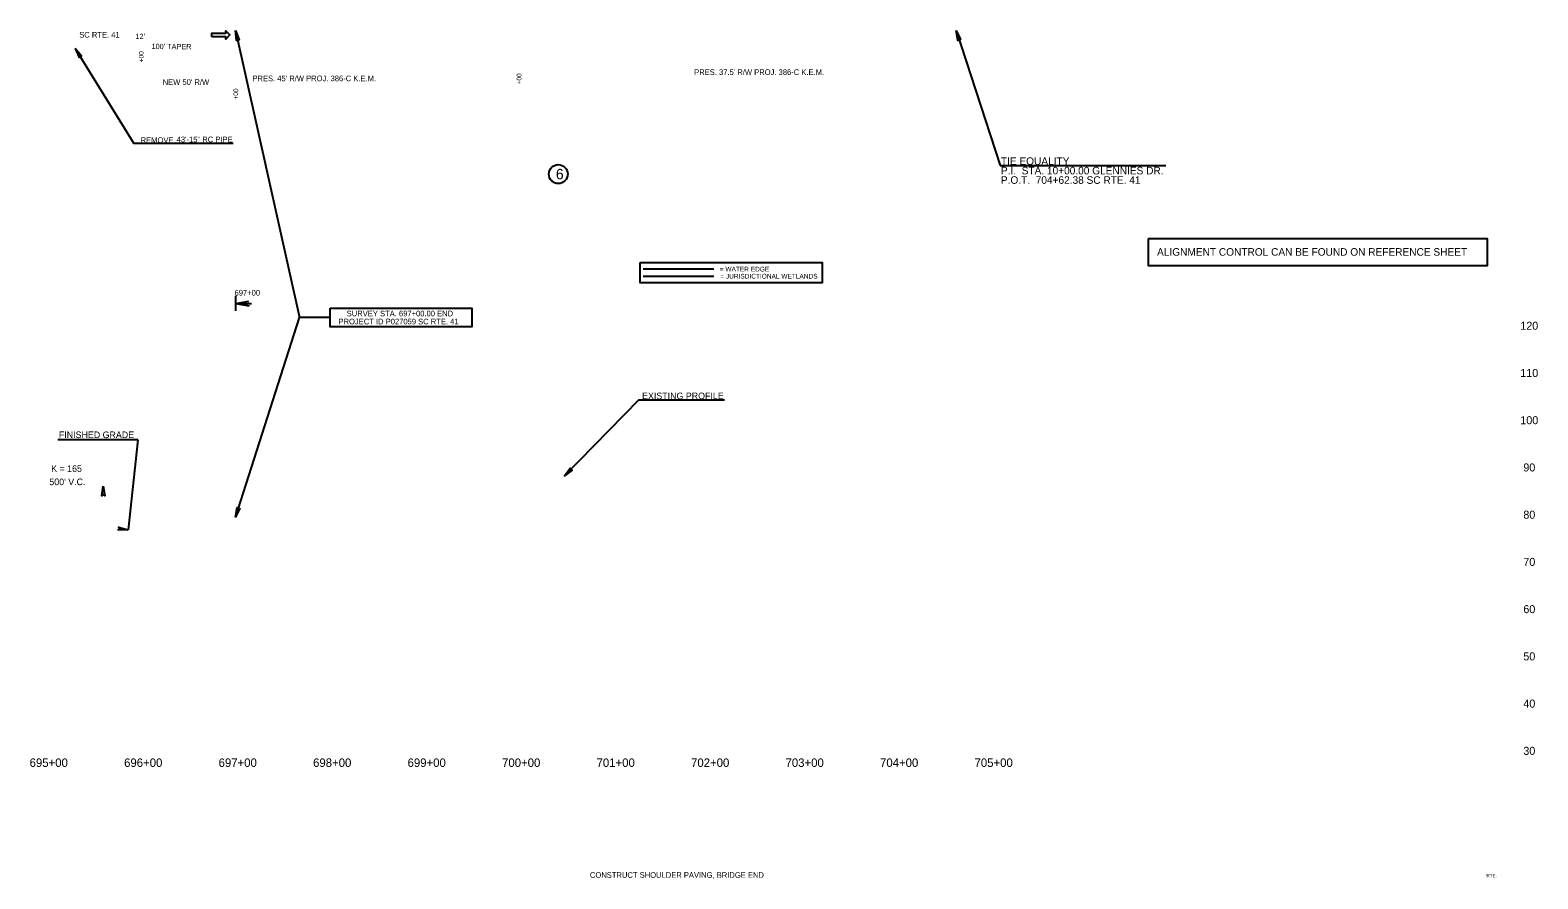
# Model space of a CAD drawing. Extents: x 2522404 to 2525275, y 885432 to 893540.
# Drawn here: x 2523395 to 2524991, y 888858 to 889756 of the extents above; entities that cross this region are included whole.
import ezdxf

# ---------------------------------------------------------------- set-up
doc = ezdxf.new("R2010")
doc.units = 0
for name, color, linetype in [('Default', 7, 'Continuous'), ('GN_Clip', 7, 'Continuous'), ('RD_DDB_ElevTX', 7, 'Continuous'), ('RD_DDB_Profile_Lbl', 7, 'Continuous'), ('RD_DDB_Profile_PR', 7, 'Continuous'), ('RD_DDB_StaTX', 7, 'Continuous'), ('RD_EV_JW', 7, 'Continuous'), ('RD_EX_H2O', 7, 'Continuous'), ('RD_EX_Misc', 7, 'Continuous'), ('RD_HC_Cl', 7, 'Continuous'), ('RD_HC_TX_Sta50', 7, 'Continuous'), ('RD_HY_TX1', 7, 'Continuous'), ('RD_PD_Final_LnLine', 7, 'Continuous'), ('RD_PD_RW_TX', 7, 'Continuous'), ('RD_SHT_IplotShp', 7, 'Continuous'), ('RD_SHT_MnGrid', 7, 'Continuous'), ('RD_Sketch1', 7, 'Continuous')]:
    doc.layers.add(name, color=color, linetype=linetype)

# ---------------------------------------------------------------- blocks, each defined once
blk = doc.blocks.new('ah_')
at = {"layer": 'Default'}
blk.add_lwpolyline([(0, 0), (-1.4, -10.4), (0, -8.8), (1.5, -10.4)], close=True, dxfattribs=at)
blk = doc.blocks.new('ah4')
at = {"layer": 'Default', "rotation": -90.00000000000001}
blk.add_blockref('ah_', (0, 0), dxfattribs=at)
blk = doc.blocks.new('AH4_')
at = {"layer": 'Default'}
blk.add_lwpolyline([(0, 0), (-10.4, 1.5), (-8.8, 0), (-10.4, -1.5)], close=True, dxfattribs=at)
blk = doc.blocks.new('AH')
at = {"layer": 'Default'}
blk.add_lwpolyline([(0, 0), (-10.4, 1.5), (-8.8, 0), (-10.4, -1.5)], close=True, dxfattribs=at)

msp = doc.modelspace()

# ---------------------------------------------------------------- linework, layer by layer
at = {"layer": 'Default'}
for p, q in [((2523612.7, 889458.8), (2523612.7, 889474.8)), ((2523612.7, 889466.8), (2523626.7, 889469.1)), ((2523612.7, 889466.8), (2523629.3, 889466.8)), ((2523612.7, 889466.8), (2523627, 889464.2))]:
    msp.add_line(p, q, dxfattribs=at)
for points in [[(2523587.5, 889749.1), (2523587.5, 889752.9), (2523602.1, 889752.9), (2523602.1, 889755.5), (2523606.6, 889751), (2523602.1, 889746.5), (2523602.1, 889749.1)], [(2524040.9, 889510.1), (2524233.4, 889510.1), (2524233.4, 889488.7), (2524040.9, 889488.7)]]:
    msp.add_lwpolyline(points, close=True, dxfattribs=at)
at = {"layer": 'RD_DDB_Profile_PR'}
msp.add_lwpolyline([(2524578.5, 889535.3), (2524578.5, 889506.9), (2524937.6, 889506.9), (2524937.6, 889535.3)], close=True, dxfattribs=at)
at = {"layer": 'RD_DDB_StaTX'}
for p, q in [((2524038.9, 889364.5), (2523960.3, 889284)), ((2524130.1, 889364.5), (2524038.9, 889364.5)), ((2523509.1, 889322.5), (2523424.3, 889322.5)), ((2523509.1, 889322.5), (2523498.8, 889227.1))]:
    msp.add_line(p, q, dxfattribs=at)
at = {"layer": 'RD_EV_JW'}
msp.add_line((2524043.8, 889495.6), (2524118.8, 889495.6), dxfattribs=at)
at = {"layer": 'RD_EX_H2O'}
msp.add_line((2524118.6, 889503.1), (2524044.1, 889503.1), dxfattribs=at)
at = {"layer": 'RD_EX_Misc'}
msp.add_circle((2523954.1, 889603.7), 10, dxfattribs=at)
at = {"layer": 'RD_HY_TX1'}
for points in [[(2523442.8, 889736.8), (2523504.9, 889636)], [(2523610.1, 889636), (2523504.9, 889636)]]:
    msp.add_lwpolyline(points, dxfattribs=at)
at = {"layer": 'RD_PD_RW_TX'}
for p, q in [((2524375, 889755.6), (2524421.6, 889612.7)), ((2524421.6, 889612.7), (2524597, 889612.7))]:
    msp.add_line(p, q, dxfattribs=at)
at = {"layer": 'RD_SHT_MnGrid'}
for p in [(2523612.6, 889755.6), (2523612.6, 889240.3), (2523712.6, 889451.9)]:
    msp.add_line(p, (2523680.4, 889451.9), dxfattribs=at)
msp.add_lwpolyline([(2523712.6, 889461.9), (2523862.6, 889461.9), (2523862.6, 889441.9), (2523712.6, 889441.9)], close=True, dxfattribs=at)

# ---------------------------------------------------------------- block references
at = {"layer": 'RD_HY_TX1', "rotation": 121.34907771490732}
msp.add_blockref('ah4', (2523442.8, 889736.8), dxfattribs=at)
at = {"layer": 'RD_PD_Final_LnLine'}
for name, p, yscale, rotation in [('AH4_', (2523612.6, 889755.6), -0.9999999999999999, 102.84799684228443), ('AH4_', (2524375, 889755.6), -1, 108.31435027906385), ('AH4_', (2523960.3, 889284), -0.9999999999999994, -135.72820993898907), ('AH', (2523472.6, 889273.4), -0.9999999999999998, 90.27255415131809), ('AH4_', (2523612.6, 889240.4), -0.9999999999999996, -107.6464303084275), ('AH', (2523498.8, 889227.1), -0.9999999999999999, -7.728553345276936)]:
    msp.add_blockref(name, p, dxfattribs=dict(at, yscale=yscale, rotation=rotation))

# ---------------------------------------------------------------- texts
at = {"layer": 'Default'}
msp.add_text('697+00', height=6, dxfattribs=at).set_placement((2523611.5, 889475.1))
at = {"layer": 'GN_Clip'}
for s, p in [('695+00', (2523394.6, 888976.1)), ('696+00', (2523494.6, 888976.1)), ('697+00', (2523594.6, 888976.1)), ('698+00', (2523694.6, 888976.1)), ('699+00', (2523794.6, 888976.1)), ('700+00', (2523894.6, 888976.1)), ('701+00', (2523994.6, 888976.1)), ('702+00', (2524094.6, 888976.1)), ('703+00', (2524194.6, 888976.1)), ('704+00', (2524294.6, 888976.1)), ('705+00', (2524394.6, 888976.1))]:
    msp.add_text(s, height=9, dxfattribs=at).set_placement(p)
at = {"layer": 'RD_DDB_ElevTX'}
for s, p in [('K = 165', (2523417.4, 889288.4)), ("500' V.C.", (2523415.5, 889274.4))]:
    msp.add_text(s, height=7, dxfattribs=at).set_placement(p)
at = {"layer": 'RD_DDB_Profile_Lbl'}
msp.add_text('6', height=11, dxfattribs=at).set_placement((2523951.6, 889598.2))
at = {"layer": 'RD_DDB_Profile_PR'}
msp.add_text('ALIGNMENT CONTROL CAN BE FOUND ON REFERENCE SHEET', height=8, dxfattribs=at).set_placement((2524587.8, 889517.3))
at = {"layer": 'RD_DDB_StaTX'}
for s, p in [("12'", (2523506.6, 889746.7)), ("100' TAPER", (2523523.6, 889736.1))]:
    msp.add_text(s, height=5.6, rotation=359.5861, dxfattribs=at).set_placement(p)
for s, height, p in [('EXISTING PROFILE', 7, (2524042.8, 889365.4)), ('FINISHED GRADE', 7, (2523425.6, 889324.2)), ('CONSTRUCT SHOULDER PAVING, BRIDGE END', 6, (2523987.6, 888858.7))]:
    msp.add_text(s, height=height, dxfattribs=at).set_placement(p)
at = {"layer": 'RD_EV_JW'}
for s, p in [('= WATER EDGE', (2524125, 889500.6)), ('= JURISDICTIONAL WETLANDS', (2524125.5, 889493.1))]:
    msp.add_text(s, height=5, dxfattribs=at).set_placement(p)
at = {"layer": 'RD_EX_Misc'}
msp.add_text('RTE.', height=3.5, dxfattribs=at).set_placement((2524936.3, 888859.3))
at = {"layer": 'RD_HC_Cl'}
for s, height, p in [('SC RTE. 41', 6, (2523447.1, 889748.2)), ('TIE EQUALITY', 8, (2524422.5, 889613.4)), ('P.I.  STA. 10+00.00 GLENNIES DR.', 8, (2524422.5, 889603.4)), ('P.O.T.  704+62.38 SC RTE. 41', 8, (2524422.5, 889593.4))]:
    msp.add_text(s, height=height, rotation=360, dxfattribs=at).set_placement(p)
at = {"layer": 'RD_HC_TX_Sta50'}
for s, p in [('120', (2524972.2, 889438.9)), ('110', (2524972.2, 889388.9)), ('100', (2524972.2, 889338.9)), ('90', (2524975.4, 889288.9)), ('80', (2524975.4, 889238.9)), ('70', (2524975.4, 889188.9)), ('60', (2524975.4, 889138.9)), ('50', (2524975.4, 889088.9)), ('40', (2524975.4, 889038.9)), ('30', (2524975.4, 888988.9))]:
    msp.add_text(s, height=8.5, dxfattribs=at).set_placement(p)
at = {"layer": 'RD_HY_TX1'}
for s, p in [('REMOVE', (2523512.1, 889636.7)), ('43\'-15" RC PIPE', (2523550.2, 889637.4))]:
    msp.add_text(s, height=6, dxfattribs=at).set_placement(p)
at = {"layer": 'RD_SHT_IplotShp'}
for s, height, rotation, p in [('+00', 5, 90, (2523515.3, 889722.1)), ("PRES. 45' R/W PROJ. 386-C K.E.M.", 6, 360, (2523630.4, 889702)), ('+00', 5, 90, (2523915.1, 889698.6)), ("PRES. 37.5' R/W PROJ. 386-C K.E.M.", 6, 360, (2524097.9, 889708.6))]:
    msp.add_text(s, height=height, rotation=rotation, dxfattribs=at).set_placement(p)
at = {"layer": 'RD_SHT_MnGrid'}
for s, p in [('SURVEY STA. 697+00.00 END ', (2523730.2, 889453.1)), ('PROJECT ID P027059 SC RTE. 41', (2523721.5, 889444.6))]:
    msp.add_text(s, height=6, dxfattribs=at).set_placement(p)
at = {"layer": 'RD_Sketch1'}
for s, height, rotation, p in [("NEW 50' R/W", 6, 360, (2523535.4, 889698.1)), ('+00', 5, 90, (2523615.3, 889682.6))]:
    msp.add_text(s, height=height, rotation=rotation, dxfattribs=at).set_placement(p)

doc.saveas('drawing.dxf')
